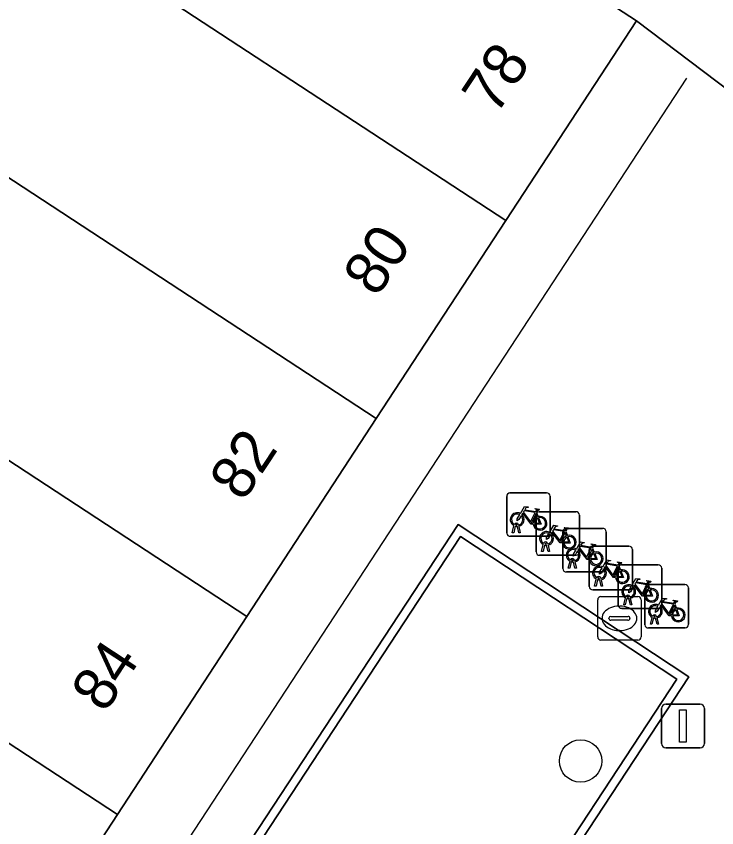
# Model space of a CAD drawing. Extents: x 155640 to 156811, y 382821 to 384049.
# Drawn here: x 156456.82 to 156472.95, y 383762.3 to 383780.99 of the extents above; entities that cross this region are included whole.
import ezdxf

# ---------------------------------------------------------------- set-up
doc = ezdxf.new("R2010")
doc.units = 0
for name, color, linetype in [('IMGEO_Boom', 7, 'Continuous'), ('IMGEO_Brandkraan', 7, 'Continuous'), ('IMGEO_Fietsenrek', 7, 'Continuous'), ('IMGEO_Lichtmast', 7, 'Continuous'), ('IMGEO_Lijnafwatering', 7, 'Continuous'), ('IMGEO_Muur', 7, 'Continuous'), ('IMGEO_Pand', 7, 'Continuous'), ('IMGEO_Pand_nummerreeks', 7, 'Continuous'), ('IMGEO_Rijbaan_lokaal_gesloten', 7, 'Continuous'), ('IMGEO_Voetgangersgebied_open', 7, 'Continuous')]:
    doc.layers.add(name, color=color, linetype=linetype)

msp = doc.modelspace()

# ---------------------------------------------------------------- linework, layer by layer
at = {"layer": 'IMGEO_Boom'}
msp.add_circle((156469.813, 383763.841), 0.489, dxfattribs=at)
at = {"layer": 'IMGEO_Brandkraan'}
for p, q in [((156470.207, 383766.7), (156470.207, 383767.552)), ((156470.282, 383767.626), (156471.134, 383767.626)), ((156471.208, 383767.552), (156471.208, 383766.7)), ((156470.695, 383767.406), (156470.72, 383767.406)), ((156470.466, 383767.12), (156470.466, 383767.132)), ((156470.904, 383767.083), (156470.506, 383767.083)), ((156470.509, 383767.169), (156470.907, 383767.169)), ((156470.95, 383767.132), (156470.95, 383767.12)), ((156470.718, 383766.846), (156470.693, 383766.846)), ((156471.134, 383766.626), (156470.282, 383766.626))]:
    msp.add_line(p, q, dxfattribs=at)
for points in [[(156470.207, 383766.7), (156470.207, 383767.552)], [(156470.282, 383767.626), (156471.134, 383767.626)], [(156471.208, 383767.552), (156471.208, 383766.7)], [(156471.134, 383766.626), (156470.282, 383766.626)]]:
    msp.add_lwpolyline(points, dxfattribs=at)
for centre, radius, start, end in [((156470.284, 383767.55), 0.0765, 91.552, 178.448), ((156470.284, 383767.55), 0.0765, 91.552, 178.448), ((156471.132, 383767.55), 0.0765, 1.552, 88.448), ((156471.132, 383767.55), 0.0765, 1.552, 88.448), ((156470.506, 383767.129), 0.0403, 85.8775, 175.7526), ((156470.503, 383767.119), 0.0366, 178.938, 274.7102), ((156470.907, 383767.126), 0.043, 264.8664, 352.4533), ((156470.911, 383767.131), 0.0386, 1.7309, 96.639), ((156470.284, 383766.702), 0.0765, 181.552, 268.448), ((156470.284, 383766.702), 0.0765, 181.552, 268.448), ((156471.132, 383766.702), 0.0765, 271.552, 358.448), ((156471.132, 383766.702), 0.0765, 271.552, 358.448)]:
    msp.add_arc(centre, radius, start, end, dxfattribs=at)
for centre, major_axis, ratio, start_param, end_param in [((156470.694, 383767.126), (-0.387, 0.002), 0.722429, 4.712389, 7.853982), ((156470.719, 383767.126), (-0.39, 0.002), 0.717154, 1.570796, 4.712389)]:
    msp.add_ellipse(centre, major_axis=major_axis, ratio=ratio, start_param=start_param, end_param=end_param, dxfattribs=at)
at = {"layer": 'IMGEO_Fietsenrek'}
for p, q in [((156468.113, 383769.089), (156468.113, 383769.93)), ((156468.113, 383769.93), (156468.113, 383769.089)), ((156468.188, 383770.014), (156469.029, 383770.014)), ((156469.029, 383770.014), (156468.188, 383770.014)), ((156469.113, 383769.939), (156469.113, 383769.098)), ((156469.113, 383769.098), (156469.113, 383769.939)), ((156468.8, 383769.563), (156468.836, 383769.468)), ((156468.862, 383769.579), (156469.703, 383769.579)), ((156469.703, 383769.579), (156468.862, 383769.579)), ((156469.787, 383769.504), (156469.787, 383768.663)), ((156469.787, 383768.663), (156469.787, 383769.504)), ((156468.787, 383768.654), (156468.787, 383769.495)), ((156468.787, 383769.495), (156468.787, 383768.654)), ((156468.24, 383769.098), (156468.279, 383769.258)), ((156468.309, 383769.246), (156468.274, 383769.098)), ((156468.351, 383769.27), (156468.35, 383769.274)), ((156468.392, 383769.098), (156468.358, 383769.24)), ((156468.382, 383769.281), (156468.383, 383769.274)), ((156468.39, 383769.244), (156468.425, 383769.098)), ((156469.479, 383769.196), (156470.32, 383769.196)), ((156470.32, 383769.196), (156469.479, 383769.196)), ((156469.038, 383769.014), (156468.197, 383769.014)), ((156468.197, 383769.014), (156469.038, 383769.014)), ((156468.274, 383769.098), (156468.24, 383769.098)), ((156468.425, 383769.098), (156468.392, 383769.098)), ((156469.404, 383768.271), (156469.404, 383769.112)), ((156469.404, 383769.112), (156469.404, 383768.271)), ((156469.474, 383769.128), (156469.51, 383769.033)), ((156470.404, 383769.121), (156470.404, 383768.28)), ((156470.404, 383768.28), (156470.404, 383769.121)), ((156468.914, 383768.663), (156468.953, 383768.823)), ((156468.983, 383768.811), (156468.948, 383768.663)), ((156469.025, 383768.835), (156469.024, 383768.839)), ((156469.066, 383768.663), (156469.032, 383768.805)), ((156469.056, 383768.846), (156469.057, 383768.839)), ((156469.064, 383768.809), (156469.099, 383768.663)), ((156470.084, 383768.785), (156470.925, 383768.785)), ((156470.925, 383768.785), (156470.084, 383768.785)), ((156469.712, 383768.579), (156468.871, 383768.579)), ((156468.871, 383768.579), (156469.712, 383768.579)), ((156468.948, 383768.663), (156468.914, 383768.663)), ((156469.099, 383768.663), (156469.066, 383768.663)), ((156470.009, 383767.86), (156470.009, 383768.701)), ((156470.009, 383768.701), (156470.009, 383767.86)), ((156470.091, 383768.745), (156470.127, 383768.65)), ((156471.009, 383768.71), (156471.009, 383767.869)), ((156471.009, 383767.869), (156471.009, 383768.71)), ((156469.531, 383768.28), (156469.57, 383768.44)), ((156469.6, 383768.428), (156469.565, 383768.28)), ((156469.642, 383768.452), (156469.641, 383768.456)), ((156469.683, 383768.28), (156469.649, 383768.422)), ((156469.673, 383768.463), (156469.674, 383768.456)), ((156469.681, 383768.426), (156469.716, 383768.28)), ((156470.329, 383768.196), (156469.488, 383768.196)), ((156469.488, 383768.196), (156470.329, 383768.196)), ((156469.565, 383768.28), (156469.531, 383768.28)), ((156469.716, 383768.28), (156469.683, 383768.28)), ((156470.681, 383767.431), (156470.681, 383768.272)), ((156470.681, 383768.272), (156470.681, 383767.431)), ((156470.696, 383768.334), (156470.732, 383768.239)), ((156470.756, 383768.356), (156471.597, 383768.356)), ((156471.597, 383768.356), (156470.756, 383768.356)), ((156471.681, 383768.281), (156471.681, 383767.44)), ((156471.681, 383767.44), (156471.681, 383768.281)), ((156470.136, 383767.869), (156470.175, 383768.029)), ((156470.205, 383768.017), (156470.17, 383767.869)), ((156470.247, 383768.041), (156470.246, 383768.045)), ((156470.288, 383767.869), (156470.254, 383768.011)), ((156470.278, 383768.052), (156470.279, 383768.045)), ((156470.286, 383768.015), (156470.321, 383767.869)), ((156470.17, 383767.869), (156470.136, 383767.869)), ((156470.321, 383767.869), (156470.288, 383767.869)), ((156471.368, 383767.905), (156471.404, 383767.81)), ((156471.37, 383767.904), (156472.211, 383767.904)), ((156472.211, 383767.904), (156471.37, 383767.904)), ((156472.295, 383767.829), (156472.295, 383766.988)), ((156472.295, 383766.988), (156472.295, 383767.829)), ((156470.934, 383767.785), (156470.093, 383767.785)), ((156470.093, 383767.785), (156470.934, 383767.785)), ((156471.295, 383766.979), (156471.295, 383767.82)), ((156471.295, 383767.82), (156471.295, 383766.979)), ((156470.808, 383767.44), (156470.847, 383767.6)), ((156470.877, 383767.588), (156470.842, 383767.44)), ((156470.919, 383767.612), (156470.918, 383767.616)), ((156470.96, 383767.44), (156470.926, 383767.582)), ((156470.95, 383767.623), (156470.951, 383767.616)), ((156470.958, 383767.586), (156470.993, 383767.44)), ((156471.982, 383767.453), (156472.018, 383767.358)), ((156471.606, 383767.356), (156470.765, 383767.356)), ((156470.765, 383767.356), (156471.606, 383767.356)), ((156470.842, 383767.44), (156470.808, 383767.44)), ((156470.993, 383767.44), (156470.96, 383767.44)), ((156471.422, 383766.988), (156471.461, 383767.148)), ((156471.491, 383767.136), (156471.456, 383766.988)), ((156471.533, 383767.16), (156471.532, 383767.164)), ((156471.574, 383766.988), (156471.54, 383767.13)), ((156471.564, 383767.171), (156471.565, 383767.164)), ((156471.572, 383767.134), (156471.607, 383766.988)), ((156472.22, 383766.904), (156471.379, 383766.904)), ((156471.379, 383766.904), (156472.22, 383766.904)), ((156471.456, 383766.988), (156471.422, 383766.988)), ((156471.607, 383766.988), (156471.574, 383766.988))]:
    msp.add_line(p, q, dxfattribs=at)
for points in [[(156468.426, 383769.54), (156468.521, 383769.704), (156468.607, 383769.69), (156468.609, 383769.681), (156468.553, 383769.67), (156468.526, 383769.625), (156468.782, 383769.584)], [(156468.447, 383769.488), (156468.395, 383769.398), (156468.355, 383769.373), (156468.356, 383769.42), (156468.411, 383769.514)], [(156468.722, 383769.296), (156468.672, 383769.296), (156468.481, 383769.547), (156468.462, 383769.515)], [(156468.769, 383769.559), (156468.512, 383769.6), (156468.495, 383769.571), (156468.662, 383769.351), (156468.769, 383769.559)], [(156468.817, 383769.461), (156468.787, 383769.538), (156468.678, 383769.32), (156468.721, 383769.32)], [(156468.782, 383769.584), (156468.807, 383769.633), (156468.801, 383769.637), (156468.778, 383769.641), (156468.766, 383769.648), (156468.765, 383769.651), (156468.767, 383769.656), (156468.862, 383769.641), (156468.864, 383769.631), (156468.854, 383769.618), (156468.842, 383769.612), (156468.828, 383769.618), (156468.8, 383769.563)], [(156468.751, 383769.32), (156468.871, 383769.319), (156468.827, 383769.433)], [(156468.847, 383769.44), (156468.902, 383769.295), (156468.752, 383769.295)], [(156469.1, 383769.105), (156469.195, 383769.269), (156469.281, 383769.255), (156469.283, 383769.246), (156469.227, 383769.235), (156469.2, 383769.19), (156469.456, 383769.149)], [(156469.443, 383769.124), (156469.186, 383769.165), (156469.169, 383769.136), (156469.336, 383768.916), (156469.443, 383769.124)], [(156469.456, 383769.149), (156469.481, 383769.198), (156469.475, 383769.202), (156469.452, 383769.206), (156469.44, 383769.213), (156469.439, 383769.216), (156469.441, 383769.221), (156469.536, 383769.206), (156469.538, 383769.196), (156469.528, 383769.183), (156469.516, 383769.177), (156469.502, 383769.183), (156469.474, 383769.128)], [(156469.121, 383769.053), (156469.069, 383768.963), (156469.029, 383768.938), (156469.03, 383768.985), (156469.085, 383769.079)], [(156469.396, 383768.861), (156469.346, 383768.861), (156469.155, 383769.112), (156469.136, 383769.08)], [(156469.491, 383769.026), (156469.461, 383769.103), (156469.352, 383768.885), (156469.395, 383768.885)], [(156469.425, 383768.885), (156469.545, 383768.884), (156469.501, 383768.998)], [(156469.521, 383769.005), (156469.576, 383768.86), (156469.426, 383768.86)], [(156469.717, 383768.722), (156469.812, 383768.886), (156469.898, 383768.872), (156469.9, 383768.863), (156469.844, 383768.852), (156469.817, 383768.807), (156470.073, 383768.766)], [(156470.06, 383768.741), (156469.803, 383768.782), (156469.786, 383768.753), (156469.953, 383768.533), (156470.06, 383768.741)], [(156470.073, 383768.766), (156470.098, 383768.815), (156470.092, 383768.819), (156470.069, 383768.823), (156470.057, 383768.83), (156470.056, 383768.833), (156470.058, 383768.838), (156470.153, 383768.823), (156470.155, 383768.813), (156470.145, 383768.8), (156470.133, 383768.794), (156470.119, 383768.8), (156470.091, 383768.745)], [(156469.738, 383768.67), (156469.686, 383768.58), (156469.646, 383768.555), (156469.647, 383768.602), (156469.702, 383768.696)], [(156470.013, 383768.478), (156469.963, 383768.478), (156469.772, 383768.729), (156469.753, 383768.697)], [(156470.108, 383768.643), (156470.078, 383768.72), (156469.969, 383768.502), (156470.012, 383768.502)], [(156470.042, 383768.502), (156470.162, 383768.501), (156470.118, 383768.615)], [(156470.138, 383768.622), (156470.193, 383768.477), (156470.043, 383768.477)], [(156470.322, 383768.311), (156470.417, 383768.475), (156470.503, 383768.461), (156470.505, 383768.452), (156470.449, 383768.441), (156470.422, 383768.396), (156470.678, 383768.355)], [(156470.678, 383768.355), (156470.703, 383768.404), (156470.697, 383768.408), (156470.674, 383768.412), (156470.662, 383768.419), (156470.661, 383768.422), (156470.663, 383768.427), (156470.758, 383768.412), (156470.76, 383768.402), (156470.75, 383768.389), (156470.738, 383768.383), (156470.724, 383768.389), (156470.696, 383768.334)], [(156470.343, 383768.259), (156470.291, 383768.169), (156470.251, 383768.144), (156470.252, 383768.191), (156470.307, 383768.285)], [(156470.618, 383768.067), (156470.568, 383768.067), (156470.377, 383768.318), (156470.358, 383768.286)], [(156470.665, 383768.33), (156470.408, 383768.371), (156470.391, 383768.342), (156470.558, 383768.122), (156470.665, 383768.33)], [(156470.713, 383768.232), (156470.683, 383768.309), (156470.574, 383768.091), (156470.617, 383768.091)], [(156470.647, 383768.091), (156470.767, 383768.09), (156470.723, 383768.204)], [(156470.743, 383768.211), (156470.798, 383768.066), (156470.648, 383768.066)], [(156470.994, 383767.882), (156471.089, 383768.046), (156471.175, 383768.032), (156471.177, 383768.023), (156471.121, 383768.012), (156471.094, 383767.967), (156471.35, 383767.926)], [(156471.015, 383767.83), (156470.963, 383767.74), (156470.923, 383767.715), (156470.924, 383767.762), (156470.979, 383767.856)], [(156471.29, 383767.638), (156471.24, 383767.638), (156471.049, 383767.889), (156471.03, 383767.857)], [(156471.337, 383767.901), (156471.08, 383767.942), (156471.063, 383767.913), (156471.23, 383767.693), (156471.337, 383767.901)], [(156471.385, 383767.803), (156471.355, 383767.88), (156471.246, 383767.662), (156471.289, 383767.662)], [(156471.35, 383767.926), (156471.375, 383767.975), (156471.369, 383767.979), (156471.346, 383767.983), (156471.334, 383767.99), (156471.333, 383767.993), (156471.335, 383767.998), (156471.43, 383767.983), (156471.432, 383767.973), (156471.422, 383767.96), (156471.41, 383767.954), (156471.396, 383767.96), (156471.368, 383767.905)], [(156471.319, 383767.662), (156471.439, 383767.661), (156471.395, 383767.775)], [(156471.415, 383767.782), (156471.47, 383767.637), (156471.32, 383767.637)], [(156471.608, 383767.43), (156471.703, 383767.594), (156471.789, 383767.58), (156471.791, 383767.571), (156471.735, 383767.56), (156471.708, 383767.515), (156471.964, 383767.474)], [(156471.951, 383767.449), (156471.694, 383767.49), (156471.677, 383767.461), (156471.844, 383767.241), (156471.951, 383767.449)], [(156471.964, 383767.474), (156471.989, 383767.523), (156471.983, 383767.527), (156471.96, 383767.531), (156471.948, 383767.538), (156471.947, 383767.541), (156471.949, 383767.546), (156472.044, 383767.531), (156472.046, 383767.521), (156472.036, 383767.508), (156472.024, 383767.502), (156472.01, 383767.508), (156471.982, 383767.453)], [(156471.629, 383767.378), (156471.577, 383767.288), (156471.537, 383767.263), (156471.538, 383767.31), (156471.593, 383767.404)], [(156471.904, 383767.186), (156471.854, 383767.186), (156471.663, 383767.437), (156471.644, 383767.405)], [(156471.999, 383767.351), (156471.969, 383767.428), (156471.86, 383767.21), (156471.903, 383767.21)], [(156471.933, 383767.21), (156472.053, 383767.209), (156472.009, 383767.323)], [(156472.029, 383767.33), (156472.084, 383767.185), (156471.934, 383767.185)]]:
    msp.add_lwpolyline(points, dxfattribs=at)
for centre, radius, start, end in [((156468.191, 383769.936), 0.0779, 92.4484, 184.2845), ((156468.191, 383769.936), 0.0779, 92.4484, 184.2845), ((156469.035, 383769.936), 0.0779, 2.4484, 94.2845), ((156469.035, 383769.936), 0.0779, 2.4484, 94.2845), ((156468.353, 383769.399), 0.159, 62.6766, 242.1369), ((156468.353, 383769.399), 0.129, 63.3192, 238.903), ((156468.353, 383769.399), 0.159, 283.5766, 46.6042), ((156468.865, 383769.501), 0.0779, 92.4484, 184.2845), ((156468.865, 383769.501), 0.0779, 92.4484, 184.2845), ((156469.709, 383769.501), 0.0779, 2.4484, 94.2845), ((156469.709, 383769.501), 0.0779, 2.4484, 94.2845), ((156468.333, 383769.27), 0.0499, 12.8025, 158.6934), ((156468.353, 383769.399), 0.129, 283.6043, 43.4302), ((156468.88, 383769.315), 0.159, 113.3408, 178.3217), ((156468.88, 383769.315), 0.159, 187.0065, 105.7708), ((156468.88, 383769.315), 0.129, 113.923, 177.9556), ((156468.88, 383769.315), 0.129, 188.6715, 104.5883), ((156468.353, 383769.399), 0.159, 253.9967, 271.7867), ((156468.333, 383769.27), 0.0174, 12.8025, 163.4502), ((156468.353, 383769.399), 0.129, 253.415, 269.0204), ((156469.482, 383769.118), 0.0779, 92.4484, 184.2845), ((156469.482, 383769.118), 0.0779, 92.4484, 184.2845), ((156470.326, 383769.118), 0.0779, 2.4484, 94.2845), ((156470.326, 383769.118), 0.0779, 2.4484, 94.2845), ((156468.191, 383769.092), 0.0779, 182.4484, 274.2845), ((156468.191, 383769.092), 0.0779, 182.4484, 274.2845), ((156469.027, 383768.964), 0.159, 62.6766, 242.1369), ((156469.027, 383768.964), 0.129, 63.3192, 238.903), ((156469.035, 383769.092), 0.0779, 272.4484, 4.2845), ((156469.035, 383769.092), 0.0779, 272.4484, 4.2845), ((156469.027, 383768.964), 0.129, 283.6043, 43.4302), ((156469.027, 383768.964), 0.159, 283.5766, 46.6042), ((156469.554, 383768.88), 0.159, 113.3408, 178.3217), ((156469.554, 383768.88), 0.159, 187.0065, 105.7708), ((156469.554, 383768.88), 0.129, 113.923, 177.9556), ((156469.554, 383768.88), 0.129, 188.6715, 104.5883), ((156469.007, 383768.835), 0.0499, 12.8025, 158.6934), ((156469.027, 383768.964), 0.159, 253.9967, 271.7867), ((156469.007, 383768.835), 0.0174, 12.8025, 163.4502), ((156469.027, 383768.964), 0.129, 253.415, 269.0204), ((156470.087, 383768.707), 0.0779, 92.4484, 184.2845), ((156470.087, 383768.707), 0.0779, 92.4484, 184.2845), ((156470.931, 383768.707), 0.0779, 2.4484, 94.2845), ((156470.931, 383768.707), 0.0779, 2.4484, 94.2845), ((156468.865, 383768.657), 0.0779, 182.4484, 274.2845), ((156468.865, 383768.657), 0.0779, 182.4484, 274.2845), ((156469.644, 383768.581), 0.159, 62.6766, 242.1369), ((156469.644, 383768.581), 0.129, 63.3192, 238.903), ((156469.644, 383768.581), 0.129, 283.6043, 43.4302), ((156469.644, 383768.581), 0.159, 283.5766, 46.6042), ((156469.709, 383768.657), 0.0779, 272.4484, 4.2845), ((156469.709, 383768.657), 0.0779, 272.4484, 4.2845), ((156470.171, 383768.497), 0.159, 113.3408, 178.3217), ((156470.171, 383768.497), 0.159, 187.0065, 105.7708), ((156470.171, 383768.497), 0.129, 113.923, 177.9556), ((156470.171, 383768.497), 0.129, 188.6715, 104.5883), ((156469.624, 383768.452), 0.0499, 12.8025, 158.6934), ((156469.644, 383768.581), 0.159, 253.9967, 271.7867), ((156469.624, 383768.452), 0.0174, 12.8025, 163.4502), ((156469.644, 383768.581), 0.129, 253.415, 269.0204), ((156469.482, 383768.274), 0.0779, 182.4484, 274.2845), ((156469.482, 383768.274), 0.0779, 182.4484, 274.2845), ((156470.249, 383768.17), 0.159, 62.6766, 242.1369), ((156470.249, 383768.17), 0.129, 63.3192, 238.903), ((156470.249, 383768.17), 0.129, 283.6043, 43.4302), ((156470.249, 383768.17), 0.159, 283.5766, 46.6042), ((156470.326, 383768.274), 0.0779, 272.4484, 4.2845), ((156470.326, 383768.274), 0.0779, 272.4484, 4.2845), ((156470.776, 383768.086), 0.159, 113.3408, 178.3217), ((156470.776, 383768.086), 0.159, 187.0065, 105.7708), ((156470.776, 383768.086), 0.129, 113.923, 177.9556), ((156470.776, 383768.086), 0.129, 188.6715, 104.5883), ((156470.759, 383768.278), 0.0779, 92.4484, 184.2845), ((156470.759, 383768.278), 0.0779, 92.4484, 184.2845), ((156471.603, 383768.278), 0.0779, 2.4484, 94.2845), ((156471.603, 383768.278), 0.0779, 2.4484, 94.2845), ((156470.229, 383768.041), 0.0499, 12.8025, 158.6934), ((156470.249, 383768.17), 0.159, 253.9967, 271.7867), ((156470.229, 383768.041), 0.0174, 12.8025, 163.4502), ((156470.249, 383768.17), 0.129, 253.415, 269.0204), ((156470.087, 383767.863), 0.0779, 182.4484, 274.2845), ((156470.087, 383767.863), 0.0779, 182.4484, 274.2845), ((156470.921, 383767.741), 0.159, 62.6766, 242.1369), ((156470.921, 383767.741), 0.129, 63.3192, 238.903), ((156470.931, 383767.863), 0.0779, 272.4484, 4.2845), ((156470.931, 383767.863), 0.0779, 272.4484, 4.2845), ((156470.921, 383767.741), 0.129, 283.6043, 43.4302), ((156470.921, 383767.741), 0.159, 283.5766, 46.6042), ((156471.373, 383767.826), 0.0779, 92.4484, 184.2845), ((156471.373, 383767.826), 0.0779, 92.4484, 184.2845), ((156472.217, 383767.826), 0.0779, 2.4484, 94.2845), ((156472.217, 383767.826), 0.0779, 2.4484, 94.2845), ((156470.901, 383767.612), 0.0499, 12.8025, 158.6934), ((156471.448, 383767.657), 0.159, 113.3408, 178.3217), ((156471.448, 383767.657), 0.159, 187.0065, 105.7708), ((156471.448, 383767.657), 0.129, 113.923, 177.9556), ((156471.448, 383767.657), 0.129, 188.6715, 104.5883), ((156470.921, 383767.741), 0.159, 253.9967, 271.7867), ((156470.901, 383767.612), 0.0174, 12.8025, 163.4502), ((156470.921, 383767.741), 0.129, 253.415, 269.0204), ((156471.535, 383767.289), 0.159, 62.6766, 242.1369), ((156470.759, 383767.434), 0.0779, 182.4484, 274.2845), ((156470.759, 383767.434), 0.0779, 182.4484, 274.2845), ((156471.535, 383767.289), 0.129, 63.3192, 238.903), ((156471.535, 383767.289), 0.129, 283.6043, 43.4302), ((156471.535, 383767.289), 0.159, 283.5766, 46.6042), ((156471.603, 383767.434), 0.0779, 272.4484, 4.2845), ((156471.603, 383767.434), 0.0779, 272.4484, 4.2845), ((156472.062, 383767.205), 0.159, 113.3408, 178.3217), ((156472.062, 383767.205), 0.159, 187.0065, 105.7708), ((156472.062, 383767.205), 0.129, 113.923, 177.9556), ((156472.062, 383767.205), 0.129, 188.6715, 104.5883), ((156471.515, 383767.16), 0.0499, 12.8025, 158.6934), ((156471.535, 383767.289), 0.159, 253.9967, 271.7867), ((156471.515, 383767.16), 0.0174, 12.8025, 163.4502), ((156471.535, 383767.289), 0.129, 253.415, 269.0204), ((156471.373, 383766.982), 0.0779, 182.4484, 274.2845), ((156471.373, 383766.982), 0.0779, 182.4484, 274.2845), ((156472.217, 383766.982), 0.0779, 272.4484, 4.2845), ((156472.217, 383766.982), 0.0779, 272.4484, 4.2845)]:
    msp.add_arc(centre, radius, start, end, dxfattribs=at)
at = {"layer": 'IMGEO_Lichtmast'}
for p, q in [((156471.674, 383764.247), (156471.674, 383765.047)), ((156471.674, 383765.047), (156471.674, 383764.247)), ((156471.774, 383765.147), (156472.564, 383765.147)), ((156472.564, 383765.147), (156471.774, 383765.147)), ((156472.664, 383765.047), (156472.664, 383764.247)), ((156472.664, 383764.247), (156472.664, 383765.047)), ((156472.564, 383764.147), (156471.774, 383764.147)), ((156471.774, 383764.147), (156472.564, 383764.147))]:
    msp.add_line(p, q, dxfattribs=at)
msp.add_lwpolyline([(156472.094, 383765.022), (156472.244, 383765.022), (156472.244, 383764.272), (156472.094, 383764.272), (156472.094, 383765.022)], dxfattribs=at)
for centre, start, end in [((156471.774, 383765.047), 90, 180), ((156471.774, 383765.047), 90, 180), ((156472.564, 383765.047), 0, 90), ((156472.564, 383765.047), 360, 90), ((156471.774, 383764.247), 180, 270), ((156471.774, 383764.247), 180, 270), ((156472.564, 383764.247), 270, 0), ((156472.564, 383764.247), 270, 0)]:
    msp.add_arc(centre, 0.1, start, end, dxfattribs=at)
at = {"layer": 'IMGEO_Lijnafwatering'}
msp.add_lwpolyline([(156472.253, 383779.565), (156460.088, 383760.982)], dxfattribs=at)
at = {"layer": 'IMGEO_Muur'}
for points in [[(156472.306, 383765.783), (156466.993, 383769.287), (156458.99, 383757.098), (156464.303, 383753.596)], [(156459.267, 383757.155), (156467.05, 383769.009), (156472.029, 383765.726), (156464.246, 383753.873)]]:
    msp.add_lwpolyline(points, close=True, dxfattribs=at)
at = {"layer": 'IMGEO_Pand'}
for points in [[(156460.001, 383788.093), (156457.017, 383783.537), (156468.09, 383776.284), (156471.098, 383780.883)], [(156457.017, 383783.537), (156454.033, 383778.982), (156465.11, 383771.726), (156468.09, 383776.284)], [(156454.033, 383778.982), (156451.049, 383774.426), (156462.129, 383767.169), (156465.11, 383771.726)], [(156451.049, 383774.426), (156448.065, 383769.871), (156459.148, 383762.611), (156462.129, 383767.169)], [(156448.065, 383769.871), (156445.081, 383765.315), (156456.167, 383758.053), (156459.148, 383762.611)]]:
    msp.add_lwpolyline(points, close=True, dxfattribs=at)
at = {"layer": 'IMGEO_Rijbaan_lokaal_gesloten'}
msp.add_lwpolyline([(156464.246, 383753.873), (156472.029, 383765.726), (156467.05, 383769.009), (156459.267, 383757.155)], close=True, dxfattribs=at)
at = {"layer": 'IMGEO_Voetgangersgebied_open'}
for points in [[(156499.367, 383804.6), (156473.48, 383782.1), (156463.557, 383793.358), (156460.001, 383788.093), (156471.098, 383780.883), (156477.589, 383775.981), (156477.703, 383776.08), (156489.254, 383786.124), (156489.331, 383786.036), (156522.244, 383748.131)], [(156466.337, 383744.851), (156469.274, 383749.341), (156472.251, 383753.89), (156475.417, 383758.73), (156475.806, 383758.471), (156483.001, 383769.51), (156481.391, 383771.435), (156477.589, 383775.981), (156471.098, 383780.883), (156468.09, 383776.284), (156465.11, 383771.726), (156462.129, 383767.169), (156459.148, 383762.611), (156456.167, 383758.053), (156453.187, 383753.496), (156450.206, 383748.938), (156447.225, 383744.38)]]:
    msp.add_lwpolyline(points, dxfattribs=at)
msp.add_lwpolyline([(156464.303, 383753.596), (156458.99, 383757.098), (156466.993, 383769.287), (156472.306, 383765.783)], close=True, dxfattribs=at)

# ---------------------------------------------------------------- texts
at = {"layer": 'IMGEO_Pand_nummerreeks'}
for s, p in [('78', (156467.864, 383778.683)), ('80', (156465.124, 383774.494)), ('82', (156462.045, 383769.786)), ('84', (156458.862, 383764.92))]:
    msp.add_text(s, height=1, rotation=56.6197, dxfattribs=at).set_placement(p)

doc.saveas('drawing.dxf')
